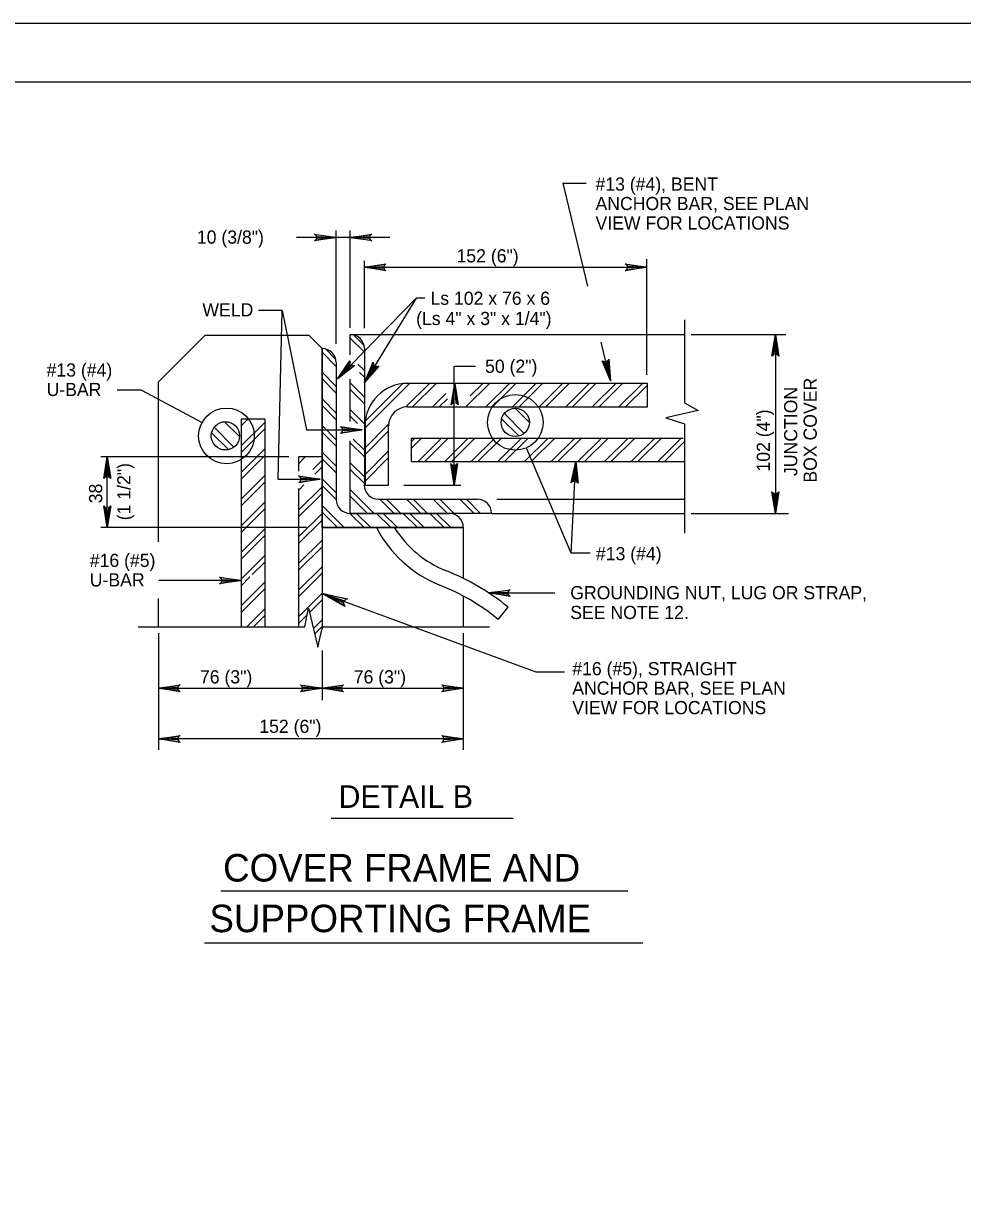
# Model space of a CAD drawing. Extents: x 638455 to 640199, y 298558 to 299152.
# Drawn here: x 638831.8 to 639071.2, y 298856.7 to 299152.2 of the extents above; entities that cross this region are included whole.
import ezdxf

# ---------------------------------------------------------------- set-up
doc = ezdxf.new("R2010")
doc.units = 0
for name, color, linetype in [('1', 7, 'Continuous'), ('2', 7, 'Continuous'), ('3', 7, 'Continuous'), ('PLT-BNDY', 7, 'Continuous')]:
    doc.layers.add(name, color=color, linetype=linetype)

msp = doc.modelspace()

# ---------------------------------------------------------------- linework, layer by layer
at = {"layer": '1'}
for p, q in [((638896.75, 299036.04), (638897.78, 299079.05)), ((638897.78, 299079.05), (638903.95, 299048.61)), ((638861.97, 299058.74), (638877.35, 299050.44))]:
    msp.add_line(p, q, dxfattribs=at)
msp.add_lwpolyline([(639279.61, 298573.25), (639279.61, 299137.25), (638493.61, 299137.25), (638493.61, 298573.25), (639279.61, 298573.25), (639279.61, 298599.61), (639079.61, 298599.61), (639079.61, 298664.29), (639279.61, 298664.29), (639279.61, 298693.25), (639079.61, 298693.25), (639079.61, 298573.25), (639158.42, 298573.25), (639158.42, 298599.61), (639158.42, 298573.25), (639235.42, 298573.25), (639235.42, 298599.61), (639235.42, 298587.29), (639279.61, 298587.29)], dxfattribs=at)
for centre in [(638957.19, 299050.51), (638883.58, 299047.06)]:
    msp.add_circle(centre, 7.09, dxfattribs=at)
at = {"layer": '2'}
for p, q in [((638969.39, 299111.46), (638975.25, 299111.46)), ((638975.66, 299085.25), (638969.39, 299111.46)), ((638911.54, 299070.52), (638911.54, 299099.43)), ((638915.12, 299074.6), (638915.12, 299099.43)), ((638915.12, 299097.63), (638901.46, 299097.63)), ((638925.2, 299097.63), (638915.12, 299097.63)), ((638990.72, 299062.65), (638990.72, 299092.12)), ((638918.72, 299074.53), (638918.72, 299091.68)), ((638918.72, 299090.03), (638990.72, 299090.03)), ((638897.78, 299079.05), (638891.73, 299079.05)), ((639000.32, 299076.63), (639000.32, 299055.51)), ((638915.12, 299072.92), (639000.32, 299072.92)), ((639002, 299072.92), (639026.16, 299072.92)), ((639023.47, 299072.92), (639023.47, 299027.32)), ((638907.97, 299069.32), (638907.94, 299069.32)), ((638907.97, 299069.32), (638907.94, 299069.32)), ((638981.44, 299061.06), (638979.08, 299070.92)), ((638941.59, 299054.45), (638941.59, 299064.82)), ((638941.77, 299064.82), (638947.04, 299064.82)), ((638861.97, 299058.74), (638855.71, 299058.74)), ((638941.59, 299034.52), (638941.59, 299054.45)), ((638893.32, 299051.35), (638887.32, 299051.35)), ((638893.32, 299051.35), (638893.32, 298998.43)), ((638903.95, 299048.61), (638918.15, 299048.61)), ((638918.89, 299049.65), (638918.89, 299034.52)), ((638924.89, 299034.52), (638924.89, 299049.65)), ((639000.32, 299050.18), (639000.32, 299022.26)), ((638971.46, 299017.15), (638960.11, 299043.77)), ((638899.49, 299041.72), (638851.54, 299041.72)), ((638853.22, 299023.72), (638853.22, 299041.72)), ((638930.72, 299040.52), (639000.32, 299040.52)), ((638896.75, 299036.04), (638907.49, 299036.04)), ((638918.89, 299034.52), (638924.89, 299034.52)), ((638928.81, 299034.52), (638943.27, 299034.52)), ((638952.46, 299030.92), (639000.32, 299030.92)), ((638951.12, 299027.32), (639000.32, 299027.32)), ((639002, 299027.32), (639026.84, 299027.32)), ((638903.96, 299023.72), (638851.54, 299023.72)), ((638907.94, 299023.72), (638907.94, 298997.92)), ((638943.94, 299023.72), (638943.94, 299023.74)), ((638943.94, 299023.72), (638943.94, 299023.74)), ((638976.26, 299017.15), (638971.46, 299017.15)), ((638887.32, 299010.21), (638866.38, 299010.21)), ((638950.38, 299007.07), (638967.25, 299007.07)), ((638952.86, 299000.3), (638955.39, 299003.4)), ((638861.11, 298998.43), (638903.56, 298998.43)), ((638908.06, 298998.43), (638950.59, 298998.43)), ((638866.27, 298996.75), (638866.27, 298967.08)), ((638943.94, 298996.75), (638943.94, 298967.08)), ((638907.94, 298992.36), (638907.94, 298979.72)), ((638866.27, 298982.74), (638907.94, 298982.74)), ((638907.94, 298982.74), (638943.94, 298982.74)), ((638943.94, 298969.83), (638866.27, 298969.83))]:
    msp.add_line(p, q, dxfattribs=at)
for points in [[(638906.31, 299098.29), (638906.5, 299097.91), (638911.54, 299097.63), (638906.31, 299098.29), (638906.04, 299098.52), (638911.54, 299097.63), (638906.51, 299097.38), (638906.32, 299097.01), (638911.54, 299097.63), (638906.04, 299096.76), (638906.32, 299097.01)], [(638920.35, 299096.97), (638920.15, 299097.35), (638915.12, 299097.63), (638920.35, 299096.97), (638920.62, 299096.75), (638915.12, 299097.63), (638920.15, 299097.88), (638920.33, 299098.26), (638915.12, 299097.63), (638920.62, 299098.51), (638920.33, 299098.26)], [(638923.95, 299089.37), (638923.75, 299089.75), (638918.72, 299090.03), (638923.95, 299089.37), (638924.22, 299089.14), (638918.72, 299090.03), (638923.75, 299090.28), (638923.93, 299090.65), (638918.72, 299090.03), (638924.22, 299090.9), (638923.93, 299090.65)], [(638985.49, 299090.69), (638985.68, 299090.31), (638990.72, 299090.03), (638985.49, 299090.69), (638985.22, 299090.92), (638990.72, 299090.03), (638985.68, 299089.78), (638985.5, 299089.41), (638990.72, 299090.03), (638985.22, 299089.16), (638985.5, 299089.41)], [(638934.1, 299082.18), (638931.9, 299082.18), (638911.87, 299061.58)], [(638931.9, 299082.18), (638918.72, 299060.71)], [(638866.27, 299020.1), (638866.27, 299060.83), (638878.15, 299072.71), (638904.55, 299072.71), (638907.94, 299069.32), (638907.94, 299023.72), (638943.94, 299023.72), (638943.94, 299010.74)], [(638915.12, 299067.73), (638915.12, 299072.92)], [(638918.72, 299068.37), (638915.12, 299071.97)], [(638918.62, 299070.16), (638915.96, 299072.82)], [(639022.81, 299067.68), (639023.19, 299067.88), (639023.47, 299072.92), (639022.81, 299067.68), (639022.58, 299067.42), (639023.47, 299072.92), (639023.72, 299067.88), (639024.09, 299067.7), (639023.47, 299072.92), (639024.34, 299067.42), (639024.09, 299067.7)], [(638943.94, 299023.72), (638907.94, 299023.72), (638907.94, 299069.32)], [(638911.44, 299066.57), (638908.79, 299069.22)], [(638918.72, 299069.34), (638918.72, 299034.56)], [(638911.54, 299064.77), (638907.94, 299068.37)], [(638911.54, 299065.74), (638911.54, 299030.89)], [(638915.92, 299064.95), (638915.51, 299065.06), (638911.87, 299061.58), (638915.92, 299064.95), (638916.27, 299064.99), (638911.87, 299061.58), (638915.13, 299065.42), (638914.98, 299065.81), (638911.87, 299061.58), (638914.99, 299066.19), (638914.98, 299065.81)], [(638922.08, 299064.76), (638921.66, 299064.8), (638918.72, 299060.71), (638922.08, 299064.76), (638922.42, 299064.87), (638918.72, 299060.71), (638921.21, 299065.08), (638920.99, 299065.44), (638918.72, 299060.71), (638920.94, 299065.82), (638920.99, 299065.44)], [(638980.87, 299066.3), (638980.54, 299066.02), (638981.44, 299061.06), (638980.87, 299066.3), (638981.03, 299066.61), (638981.44, 299061.06), (638980.03, 299065.9), (638979.62, 299065.99), (638981.44, 299061.06), (638979.32, 299066.21), (638979.62, 299065.99)], [(638911.54, 299059.68), (638907.94, 299063.28)], [(638918.72, 299063.75), (638917.09, 299065.38)], [(638918.72, 299062.05), (638917.51, 299063.26)], [(638911.54, 299057.98), (638907.94, 299061.58)], [(638915.12, 299050.74), (638915.12, 299061.53)], [(638918.72, 299056.96), (638915.12, 299060.56)], [(638918.89, 299049.13), (638930.21, 299060.45)], [(638918.89, 299050.82), (638928.51, 299060.45)], [(638929.29, 299054.43), (638935.3, 299060.45)], [(638929.69, 299054.45), (638990.89, 299054.45), (638990.89, 299060.45), (638929.69, 299060.45)], [(638931, 299054.45), (638937, 299060.45)], [(638941.11, 299055.22), (638941.49, 299055.41), (638941.77, 299060.45), (638941.11, 299055.22), (638940.88, 299054.95), (638941.77, 299060.45), (638942.01, 299055.42), (638942.39, 299055.23), (638941.77, 299060.45), (638942.64, 299054.95), (638942.39, 299055.23)], [(638944.58, 299054.45), (638950.58, 299060.45)], [(638945.71, 299057.28), (638948.88, 299060.45)], [(638949.67, 299054.45), (638955.67, 299060.45)], [(638951.36, 299054.45), (638957.36, 299060.45)], [(638956.46, 299054.45), (638962.46, 299060.45)], [(638958.15, 299054.45), (638964.15, 299060.45)], [(638963.24, 299054.45), (638969.24, 299060.45)], [(638964.94, 299054.45), (638970.94, 299060.45)], [(638970.03, 299054.45), (638976.03, 299060.45)], [(638971.73, 299054.45), (638977.73, 299060.45)], [(638976.82, 299054.45), (638982.82, 299060.45)], [(638978.52, 299054.45), (638984.52, 299060.45)], [(638983.61, 299054.45), (638989.61, 299060.45)], [(638985.31, 299054.45), (638990.89, 299060.03)], [(638918.72, 299055.26), (638915.12, 299058.86)], [(638936.09, 299054.45), (638939.47, 299057.83)], [(638911.54, 299052.89), (638907.94, 299056.49)], [(638911.54, 299051.2), (638907.94, 299054.8)], [(638918.72, 299050.17), (638915.12, 299053.77)], [(638937.79, 299054.45), (638939.89, 299056.55)], [(638960.78, 299050.47), (638957.14, 299054.11)], [(638984.39, 299054.4), (638984.37, 299054.38)], [(638984.37, 299054.38), (638984.37, 299054.4)], [(639000.32, 299055.51), (639003.75, 299053.58), (638995.58, 299051.67), (639000.32, 299050.18)], [(638887.32, 299049.61), (638889.06, 299051.35)], [(638887.32, 299051.35), (638887.32, 298998.43)], [(638917, 299050.19), (638915.12, 299052.08)], [(638957.97, 299047.17), (638953.71, 299051.43)], [(638959.46, 299047.71), (638954.4, 299052.78)], [(638884.1, 299043.57), (638879.81, 299047.86)], [(638885.5, 299044.21), (638880.45, 299049.25)], [(638886.91, 299046.87), (638883.11, 299050.67)], [(638887.32, 299044.52), (638893.32, 299050.52)], [(638887.32, 299042.83), (638893.32, 299048.83)], [(638911.54, 299046.1), (638907.94, 299049.7)], [(638911.54, 299044.41), (638907.94, 299048.01)], [(638912.91, 299049.24), (638913.11, 299048.86), (638918.15, 299048.61), (638912.91, 299049.24), (638912.65, 299049.47), (638918.15, 299048.61), (638913.12, 299048.33), (638912.94, 299047.96), (638918.15, 299048.61), (638912.65, 299047.71), (638912.94, 299047.96)], [(638918.89, 299044.04), (638924.91, 299050.05)], [(638918.89, 299042.34), (638924.89, 299048.34)], [(638951.12, 299027.32), (638915.12, 299027.32), (638915.12, 299045.83)], [(638918.72, 299041.69), (638915.12, 299045.29)], [(638918.72, 299043.39), (638915.89, 299046.22)], [(638930.72, 299040.52), (638930.72, 299046.52), (638999.94, 299046.52)], [(638930.72, 299043.92), (638933.31, 299046.52)], [(638930.72, 299045.62), (638931.62, 299046.52)], [(638932.4, 299040.52), (638938.4, 299046.52)], [(638934.1, 299040.52), (638940.1, 299046.52)], [(638939.19, 299040.52), (638945.19, 299046.52)], [(638940.89, 299040.52), (638946.89, 299046.52)], [(638945.98, 299040.52), (638951.98, 299046.52)], [(638947.68, 299040.52), (638953.68, 299046.52)], [(638952.77, 299040.52), (638958.77, 299046.52)], [(638954.47, 299040.52), (638960.47, 299046.52)], [(638959.56, 299040.52), (638965.56, 299046.52)], [(638961.25, 299040.52), (638967.25, 299046.52)], [(638966.35, 299040.52), (638972.35, 299046.52)], [(638968.04, 299040.52), (638974.04, 299046.52)], [(638973.13, 299040.52), (638979.13, 299046.52)], [(638974.83, 299040.52), (638980.83, 299046.52)], [(638979.92, 299040.52), (638985.92, 299046.52)], [(638981.62, 299040.52), (638987.62, 299046.52)], [(638986.71, 299040.52), (638992.71, 299046.52)], [(638988.41, 299040.52), (638994.41, 299046.52)], [(638993.5, 299040.52), (638999.5, 299046.52)], [(638995.2, 299040.52), (639000.32, 299045.64)], [(638887.32, 299037.73), (638893.32, 299043.73)], [(638887.32, 299036.04), (638893.32, 299042.04)], [(638911.54, 299039.32), (638907.94, 299042.92)], [(638918.89, 299037.25), (638924.89, 299043.25)], [(638930.62, 299042.22), (638930.72, 299042.47)], [(639000.29, 299044.3), (639000.32, 299044.33)], [(638852.56, 299036.48), (638852.94, 299036.68), (638853.22, 299041.72), (638852.56, 299036.48), (638852.33, 299036.22), (638853.22, 299041.72), (638853.46, 299036.68), (638853.84, 299036.5), (638853.22, 299041.72), (638854.09, 299036.22), (638853.84, 299036.5)], [(638901.94, 299039.98), (638903.68, 299041.72)], [(638907.94, 299041.72), (638901.94, 299041.72), (638901.94, 299038.07)], [(638905.58, 299038.53), (638907.94, 299040.89)], [(638906.09, 299037.34), (638907.94, 299039.19)], [(638911.54, 299037.62), (638907.94, 299041.22)], [(638918.72, 299036.6), (638915.12, 299040.2)], [(638918.89, 299035.55), (638924.89, 299041.55)], [(638942.25, 299039.75), (638941.87, 299039.55), (638941.59, 299034.52), (638942.25, 299039.75), (638942.48, 299040.01), (638941.59, 299034.52), (638941.35, 299039.55), (638940.97, 299039.73), (638941.59, 299034.52), (638940.72, 299040.01), (638940.97, 299039.73)], [(638971.46, 299017.15), (638972.62, 299040.52)], [(638971.71, 299035.32), (638972.1, 299035.5), (638972.62, 299040.52), (638971.71, 299035.32), (638971.46, 299035.07), (638972.62, 299040.52), (638972.62, 299035.48), (638972.99, 299035.27), (638972.62, 299040.52), (638973.22, 299034.98), (638972.99, 299035.27)], [(638887.32, 299030.95), (638893.32, 299036.95)], [(638902.25, 299036.67), (638902.45, 299036.29), (638907.49, 299036.04), (638902.25, 299036.67), (638901.98, 299036.9), (638907.49, 299036.04), (638902.46, 299035.77), (638902.27, 299035.39), (638907.49, 299036.04), (638901.99, 299035.14), (638902.27, 299035.39)], [(638911.54, 299032.53), (638907.94, 299036.13)], [(638918.72, 299034.9), (638915.12, 299038.5)], [(638887.32, 299029.25), (638893.32, 299035.25)], [(638901.94, 299033.19), (638903.33, 299034.58)], [(638901.94, 299028.1), (638907.94, 299034.1)], [(638901.94, 299033.68), (638901.94, 298998.43)], [(638911.54, 299030.83), (638907.94, 299034.43)], [(638921.21, 299027.32), (638915.12, 299033.41)], [(638887.32, 299024.16), (638893.32, 299030.16)], [(638901.94, 299026.4), (638907.94, 299032.4)], [(638919.51, 299027.32), (638915.12, 299031.71)], [(638922.29, 299030.92), (638947.54, 299030.92)], [(638926.3, 299027.32), (638922.7, 299030.92)], [(638928, 299027.32), (638924.4, 299030.92)], [(638933.09, 299027.32), (638929.49, 299030.92)], [(638934.79, 299027.32), (638931.19, 299030.92)], [(638939.88, 299027.32), (638936.28, 299030.92)], [(638941.58, 299027.32), (638937.98, 299030.92)], [(638946.67, 299027.32), (638943.07, 299030.92)], [(638948.36, 299027.32), (638944.76, 299030.92)], [(639024.12, 299032.55), (639023.75, 299032.35), (639023.47, 299027.32), (639024.12, 299032.55), (639024.35, 299032.81), (639023.47, 299027.32), (639023.22, 299032.35), (639022.84, 299032.53), (639023.47, 299027.32), (639022.59, 299032.81), (639022.84, 299032.53)], [(638853.87, 299028.95), (638853.49, 299028.75), (638853.22, 299023.72), (638853.87, 299028.95), (638854.1, 299029.21), (638853.22, 299023.72), (638852.97, 299028.75), (638852.59, 299028.93), (638853.22, 299023.72), (638852.34, 299029.21), (638852.59, 299028.93)], [(638887.32, 299022.46), (638893.32, 299028.46)], [(638901.94, 299021.31), (638907.94, 299027.31)], [(638913.57, 299023.72), (638907.94, 299029.34)], [(638911.87, 299023.72), (638907.94, 299027.64)], [(638918.66, 299023.72), (638915.06, 299027.32)], [(638915.12, 299027.32), (638940.37, 299027.32)], [(638920.35, 299023.72), (638916.75, 299027.32)], [(638925.45, 299023.72), (638921.85, 299027.32)], [(638927.14, 299023.72), (638923.54, 299027.32)], [(638932.23, 299023.72), (638928.63, 299027.32)], [(638933.93, 299023.72), (638930.33, 299027.32)], [(638939.02, 299023.72), (638935.42, 299027.32)], [(638940.72, 299023.72), (638937.12, 299027.32)], [(638901.94, 299019.61), (638907.94, 299025.61)], [(638887.32, 299017.37), (638893.32, 299023.37)], [(638887.32, 299015.67), (638893.32, 299021.67)], [(638928.86, 299023.72), (638928.6, 299023.55)], [(638935.05, 299023.53), (638935, 299023.72)], [(638935.17, 299023.72), (638935.05, 299023.53)], [(638901.94, 299014.52), (638907.94, 299020.52)], [(638901.94, 299012.82), (638907.94, 299018.82)], [(638887.32, 299010.58), (638893.32, 299016.58)], [(638890.15, 299011.71), (638893.32, 299014.88)], [(638901.94, 299007.73), (638907.94, 299013.73)], [(638882.09, 299010.87), (638882.29, 299010.49), (638887.32, 299010.21), (638882.09, 299010.87), (638881.82, 299011.1), (638887.32, 299010.21), (638882.29, 299009.96), (638882.11, 299009.59), (638887.32, 299010.21), (638881.82, 299009.34), (638882.11, 299009.59)], [(638887.32, 299008.88), (638889.55, 299011.11)], [(638887.32, 299003.78), (638893.32, 299009.78)], [(638901.94, 299006.04), (638907.94, 299012.04)], [(638887.32, 299002.08), (638893.32, 299008.08)], [(638901.94, 299000.95), (638907.94, 299006.95)], [(638969.74, 298986.89), (638962.52, 298986.89), (638907.94, 299006.92)], [(638913.54, 299003.97), (638913.48, 299004.48), (638907.94, 299006.92), (638913.54, 299003.97), (638913.74, 299003.6), (638907.94, 299006.92), (638913.7, 299005.07), (638914.06, 299005.42), (638907.94, 299006.92), (638914.49, 299005.58), (638914.06, 299005.42)], [(638955.6, 299006.35), (638955.41, 299006.73), (638950.38, 299007.07), (638955.6, 299006.35), (638955.87, 299006.11), (638950.38, 299007.07), (638955.41, 299007.25), (638955.6, 299007.63), (638950.38, 299007.07), (638955.89, 299007.87), (638955.6, 299007.63)], [(638866.27, 298998.43), (638866.27, 299005.65)], [(638904.77, 299002.07), (638907.94, 299005.25)], [(638943.94, 299006.24), (638943.94, 298998.43)], [(638888.76, 298998.43), (638893.32, 299002.99)], [(638890.46, 298998.43), (638893.32, 299001.29)], [(638901.94, 298999.25), (638904.17, 299001.48)], [(638903.56, 298998.43), (638904.51, 299003.17), (638906.83, 298993.22), (638908.06, 298998.43)], [(638905.73, 298997.94), (638907.94, 299000.16)], [(638906.05, 298996.57), (638907.94, 298998.46)], [(638906.69, 298993.81), (638907.05, 298994.18)], [(638871.5, 298982.08), (638871.3, 298982.46), (638866.27, 298982.74), (638871.5, 298982.08), (638871.77, 298981.85), (638866.27, 298982.74), (638871.3, 298982.99), (638871.48, 298983.36), (638866.27, 298982.74), (638871.77, 298983.61), (638871.48, 298983.36)], [(638902.71, 298983.39), (638902.9, 298983.01), (638907.94, 298982.74), (638902.71, 298983.39), (638902.44, 298983.62), (638907.94, 298982.74), (638902.91, 298982.49), (638902.72, 298982.11), (638907.94, 298982.74), (638902.44, 298981.86), (638902.72, 298982.11)], [(638913.17, 298982.08), (638912.98, 298982.46), (638907.94, 298982.74), (638913.17, 298982.08), (638913.44, 298981.85), (638907.94, 298982.74), (638912.97, 298982.99), (638913.16, 298983.36), (638907.94, 298982.74), (638913.44, 298983.61), (638913.16, 298983.36)], [(638938.71, 298983.39), (638938.9, 298983.01), (638943.94, 298982.74), (638938.71, 298983.39), (638938.44, 298983.62), (638943.94, 298982.74), (638938.91, 298982.49), (638938.72, 298982.11), (638943.94, 298982.74), (638938.44, 298981.86), (638938.72, 298982.11)], [(638871.5, 298969.18), (638871.3, 298969.56), (638866.27, 298969.83), (638871.5, 298969.18), (638871.77, 298968.95), (638866.27, 298969.83), (638871.3, 298970.08), (638871.48, 298970.46), (638866.27, 298969.83), (638871.77, 298970.71), (638871.48, 298970.46)], [(638938.71, 298970.49), (638938.9, 298970.11), (638943.94, 298969.83), (638938.71, 298970.49), (638938.44, 298970.72), (638943.94, 298969.83), (638938.91, 298969.58), (638938.72, 298969.21), (638943.94, 298969.83), (638938.44, 298968.96), (638938.72, 298969.21)]]:
    msp.add_lwpolyline(points, dxfattribs=at)
for centre in [(638957.19, 299050.51), (638883.32, 299047.08)]:
    msp.add_circle(centre, 3.6, dxfattribs=at)
for centre, radius, start, end in [((638915.14, 299069.34), 3.58, 0, 90), ((638907.96, 299065.74), 3.58, 0, 90), ((638929.69, 299049.65), 10.8, 90, 180), ((638929.69, 299049.65), 4.8, 90, 180), ((638922.29, 299034.49), 3.58, 180, 270), ((638915.12, 299030.89), 3.58, 180, 270), ((638947.54, 299027.34), 3.58, 0, 90), ((638940.36, 299023.74), 3.58, 0, 90), ((638949.68, 299038.13), 31.38, 207.3417, 247.994), ((638949.68, 299038.13), 27.38, 211.9276, 247.994), ((638917.14, 298956.35), 60.64, 50.8947, 68.4711), ((638917.14, 298956.35), 56.64, 50.8947, 68.4711)]:
    msp.add_arc(centre, radius, start, end, dxfattribs=at)
at = {"layer": '3'}
for p, q in [((638910.24, 298949.62), (638956.67, 298949.62)), ((638882.14, 298931.11), (638985.91, 298931.11)), ((638878.01, 298917.86), (638989.7, 298917.86))]:
    msp.add_line(p, q, dxfattribs=at)
at = {"layer": 'PLT-BNDY'}
msp.add_lwpolyline([(638454.61, 299152.25), (639295.61, 299152.25), (639295.61, 298558.25), (638454.61, 298558.25)], close=True, dxfattribs=at)

# ---------------------------------------------------------------- texts
at = {"layer": '1'}
msp.add_text('(Ls 4" x 3" x 1/4")', height=3.36, dxfattribs=at).set_placement((638931.92, 299075.32))
at = {"layer": '3'}
for s, height, p in [('#13 (#4), BENT', 3.36, (638977.63, 299109.57)), ('ANCHOR BAR, SEE PLAN', 3.36, (638977.63, 299104.61)), ('VIEW FOR LOCATIONS', 3.36, (638977.63, 299099.65)), ('10 (3/8")', 3.36, (638876.04, 299096.05)), ('152 (6")', 3.36, (638942.21, 299091.28)), ('Ls 102 x 76 x 6', 3.36, (638935.57, 299080.47)), ('WELD', 3.36, (638877.45, 299077.53)), ('#13 (#4)', 3.36, (638837.74, 299062.18)), ('50 (2")', 3.36, (638949.49, 299063.14)), ('U-BAR', 3.36, (638837.74, 299057.22)), ('#13 (#4)', 3.36, (638977.74, 299015.37)), ('#16 (#5)', 3.36, (638848.75, 299013.65)), ('U-BAR', 3.36, (638848.75, 299008.69)), ('GROUNDING NUT, LUG OR STRAP,', 3.36, (638971.19, 299005.43)), ('SEE NOTE 12.', 3.36, (638971.19, 299000.39)), ('#16 (#5), STRAIGHT', 3.36, (638971.71, 298986.06)), ('76 (3")', 3.36, (638876.83, 298983.98)), ('76 (3")', 3.36, (638916.02, 298983.98)), ('ANCHOR BAR, SEE PLAN', 3.36, (638971.71, 298981.1)), ('VIEW FOR LOCATIONS', 3.36, (638971.71, 298976.14)), ('152 (6")', 3.36, (638891.95, 298971.37)), ('DETAIL B', 5.76, (638912.16, 298952.26)), ('COVER FRAME AND', 7, (638882.72, 298933.49)), ('SUPPORTING FRAME', 7, (638879.24, 298920.58))]:
    msp.add_text(s, height=height, dxfattribs=at).set_placement(p)
for s, p in [('BOX COVER', (639034.02, 299035.16)), ('JUNCTION', (639029.06, 299036.84)), ('102 (4")', (639022.08, 299037.98)), ('(1 1/2")', (638859.11, 299025.56)), ('38', (638851.91, 299029.89))]:
    msp.add_text(s, height=3.36, rotation=90, dxfattribs=at).set_placement(p)

doc.saveas('drawing.dxf')
